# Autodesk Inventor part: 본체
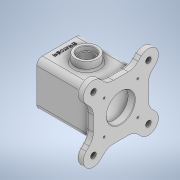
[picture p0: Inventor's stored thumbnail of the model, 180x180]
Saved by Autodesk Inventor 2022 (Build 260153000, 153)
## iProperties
Created: 2022-05
Part Number: 본체
Material: 일반
Document SubType Name: Modeling
Designer: Admin
Density: 1 g/cm^3
Appearance: 기본값
Author: Admin
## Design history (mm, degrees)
sketch "스케치1"
  geometry: L1 (-56, 0)-(56, 0) reference; L2 (0, -56)-(0, 56) reference; L3 (40, 40)-(-40, 40); L4 (-40, 40)-(-40, -40); L5 (-40, -40)-(40, -40); L6 (40, -40)-(40, 40); 1 further point
  constraints: 8 end point, 2 parallel, 1 horizontal, 1 perpendicular, 2 other
  dimensions: "d0" = 80 distance between parallel lines of L3 L5; "d1" = 80 distance of L4.end L5.end
extrude "돌출1" new body sketch "스케치1" stored distance "d2" = 98; taper "d3" = 0 deg
sketch "스케치2"
  geometry: L1 (-49, 25)-(-37, 25); L2 (-37, 25)-(-37, 35); L3 (-37, 35)-(49, 35); L4 (49, -40)-(49, 40) reference; L5 (-49, 40)-(-49, -40) reference; L6 (-49, 25)-(-49, 0); L7 (-49, 0)-(49, 0); L8 (49, 35)-(49, 0); L9 (-68.6, 0)-(68.6, 0) reference; L10 (0, -56)-(0, 56) reference; 1 further point
  constraints: 12 end point, 2 midpoint, 2 perpendicular, 2 point on line, 1 collinear, 1 horizontal
  dimensions: "d4" = 50 diameter of L1 L9; "d5" = 70 diameter of L3 L9; "d6" = 12 distance between parallel lines of L2 L5
revolve "회전1" sketch "스케치2" stored, may be unused: angle "d7" = 90 deg
sketch "스케치3"
  geometry: L1 (-49, 49)-(49, 49); L2 (49, 49)-(49, -49); L3 (49, -49)-(-49, -49); L4 (-49, -49)-(-49, 49); L5 (117.2, 0)-(-87.2, 0) reference; L6 (0, -102.6)-(0, 111.6) reference; 1 further point
  constraints: 8 end point, 2 parallel, 1 horizontal, 1 perpendicular, 2 other
  dimensions: "d8" = 98 distance of L3.end L1.start; "d9" = 98 distance of L1.start L1.end
extrude "돌출2" join sketch "스케치3" distance "d10" = 12; taper "d11" = 0 deg
sketch "스케치4"
  geometry: C1 r 35 at (0, 0) reference; C2 r 25 at (0, 0); 1 further point
  constraints: 1 centre point, 1 coincident
  dimensions: "d12" = 50 diameter of C2
extrude "돌출3" cut sketch "스케치4" distance "d13" = 12; taper "d14" = 0 deg
node "작업 평면1"
sketch "스케치6"
  geometry: L1 (-49, -49)-(-49, 49) reference; C1 r 20 at (0, 0); 1 further point
  constraints: 1 centre point, 1 coincident
  dimensions: "d18" = 40 diameter of C1; "d19" = 49 distance from line of L1 C1.centre
extrude "돌출4" join sketch "스케치6" stored distance "d20" = 12; taper "d21" = 0 deg
sketch "스케치7"
  geometry: C1 r 15 at (0, 0); 1 further point
  constraints: 1 centre point, 1 coincident
  dimensions: "d22" = 30 diameter of C1
extrude "돌출5" cut sketch "스케치7" distance "d23" = 8; taper "d24" = 0 deg
sketch "스케치8"
  geometry: C1 r 12.5 at (0, 0); 1 further point
  constraints: 1 centre point, 1 coincident
  dimensions: "d25" = 25 diameter of C1
extrude "돌출6" cut sketch "스케치8" stored distance "d26" = 0; taper "d27" = 0 deg
sketch "스케치10"
  geometry: L1 (0, -98)-(0, 98) reference; L2 (98, 0)-(-98, 0) reference; L3 (0, 0)-(-65.502, 65.502); L4 (0, 0)-(65.502, 65.502); L5 (0, 0)-(-65.502, -65.502); L6 (0, 0)-(65.502, -65.502); L7 (-49, 49)-(-49, -49) reference; L8 (-61.728, 36.272)-(-49, 23.544); L9 (-36.272, 61.728)-(-23.544, 49); L10 (49, 49)-(-49, 49) reference; L11 (-49, 23.544)-(-49, 49); L12 (-23.544, 49)-(-49, 49); A1 r 70 centre (0, 0) between (-35.171, 60.523) and (-60.523, 35.171); A2 r 18 centre (-49, 49) between (-35.171, 60.523) and (-60.523, 35.171); A3 r 18 centre (-49, 49) between (-31, 49) and (-35.171, 60.523); A4 r 18 centre (-49, 49) between (-60.523, 35.171) and (-31, 49); 1 further point
  constraints: 16 end point, 10 point on circle, 4 centre point, 4 tangent, 3 point on line, 3 symmetric about line, 2 parallel, 1 coincident, 1 collinear, 1 perpendicular
  dimensions: "d28" = 70 radius of A1; "d29" = 45 deg angle of L1 L3; "d30" = 36 diameter of A2
extrude "돌출7" join sketch "스케치10" distance "d31" = 12; taper "d32" = 0 deg
sketch "스케치11"
  geometry: C1 r 9 at (49, -49); C2 r 9 at (-49, -49); C3 r 9 at (-49, 49); C4 r 9 at (49, 49); A1 r 18 centre (49, -49) between (36.272, -61.728) and (61.728, -36.272) reference; A2 r 18 centre (-49, -49) between (-61.728, -36.272) and (-36.272, -61.728) reference; A3 r 18 centre (-49, 49) between (-36.272, 61.728) and (-61.728, 36.272) reference; A4 r 18 centre (49, 49) between (61.728, 36.272) and (36.272, 61.728) reference; 1 further point
  constraints: 4 centre point, 4 coincident
  dimensions: "d33" = 18 diameter of C1; "d34" = 18 diameter of C2; "d35" = 18 diameter of C3; "d36" = 18 diameter of C4
extrude "돌출8" cut sketch "스케치11" distance "d37" = 4; taper "d38" = 0 deg
sketch "스케치12"
  geometry: C1 r 9 at (49, -49) reference; C2 r 9 at (-49, -49) reference; C3 r 9 at (-49, 49) reference; C4 r 9 at (49, 49) reference; C5 r 5 at (49, -49); C6 r 5 at (-49, -49); C7 r 5 at (-49, 49); C8 r 5 at (49, 49); 1 further point
  constraints: 4 centre point, 4 coincident
  dimensions: "d39" = 10 diameter of C5; "d40" = 10 diameter of C6; "d41" = 10 diameter of C7; "d42" = 10 diameter of C8
extrude "돌출9" cut sketch "스케치12" extent not by distance; stored distance "d43" = 0; taper "d44" = 0 deg
sketch "스케치13"
  geometry: L1 (0, 0)-(0, 80) reference; 2 further points
  constraints: 1 horizontal alignment, 1 other
  dimensions: "d45" = 10 distance from line of L1 point (10, 40)
feature "엠보싱1" sketch "스케치13" dims "d46" = 0.5, "d47" = 0
fillet "모깎기1" dims "d48" = 25
fillet "모깎기2" dims "d49" = 10
fillet "모깎기3" dims "d50" = 3
fillet "모깎기4" dims "d51" = 3
sketch "스케치14"
  geometry: L1 (0, -93.8)-(0, 93.8) reference; L2 (93.8, 0)-(-93.8, 0) reference; L3 (-30, 30)-(30, 30); L4 (30, 30)-(30, -30); L5 (30, -30)-(-30, -30); L6 (-30, -30)-(-30, 30); L7 (30, -30)-(-30, 30); L8 (-30, -30)-(30, 30); 5 further points
  constraints: 12 end point, 4 coincident, 2 parallel, 1 horizontal, 1 perpendicular, 2 other
  dimensions: "d52" = 60 distance of L3.end L4.end; "d53" = 60 distance of L3.start L3.end
hole "구멍1" sketch "스케치14" at (-30, 30), (30, 30), (30, -30), (-30, -30) diameter "d54" = 3.242; stored, may be unused: countersink angle "d58" = 90 deg, drill point angle "d60" = 118 deg; dims "d55" = 8, "d56" = 4, "d57" = 2, "d59" = 10
chamfer "모따기1" distance "d61" = 1; stored, may be unused: second distance "d62" = 2, angle "d63" = 45 deg
fillet "모깎기5" dims "d64" = 3
sketch "스케치15"
  geometry: C1 r 1.621 at (-30, -30) reference; C2 r 1.621 at (-30, 30) reference; C3 r 1.621 at (30, 30) reference; C4 r 1.621 at (30, -30) reference; 1 further point
hole "구멍2" sketch "스케치15" at (-30, -30), (-30, 30), (30, 30), (30, -30) diameter "d65" = 3.242; stored, may be unused: countersink angle "d69" = 90 deg, drill point angle "d71" = 118 deg; dims "d66" = 8, "d67" = 4, "d68" = 2, "d70" = 10
node "솔리드1"
mirror "미러1"
mirror "미러2"
feature "A9D066F2-1C7D-4E18-AEED-F7BC21143FA4" dims "d54" = 3.242, "d55" = 8, "d56" = 4, "d57" = 2, "d58" = 90 deg, "d59" = 10, "d60" = 118 deg
other parameters: "d17" = 55
